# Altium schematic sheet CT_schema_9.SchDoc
size 274 x 160 mm
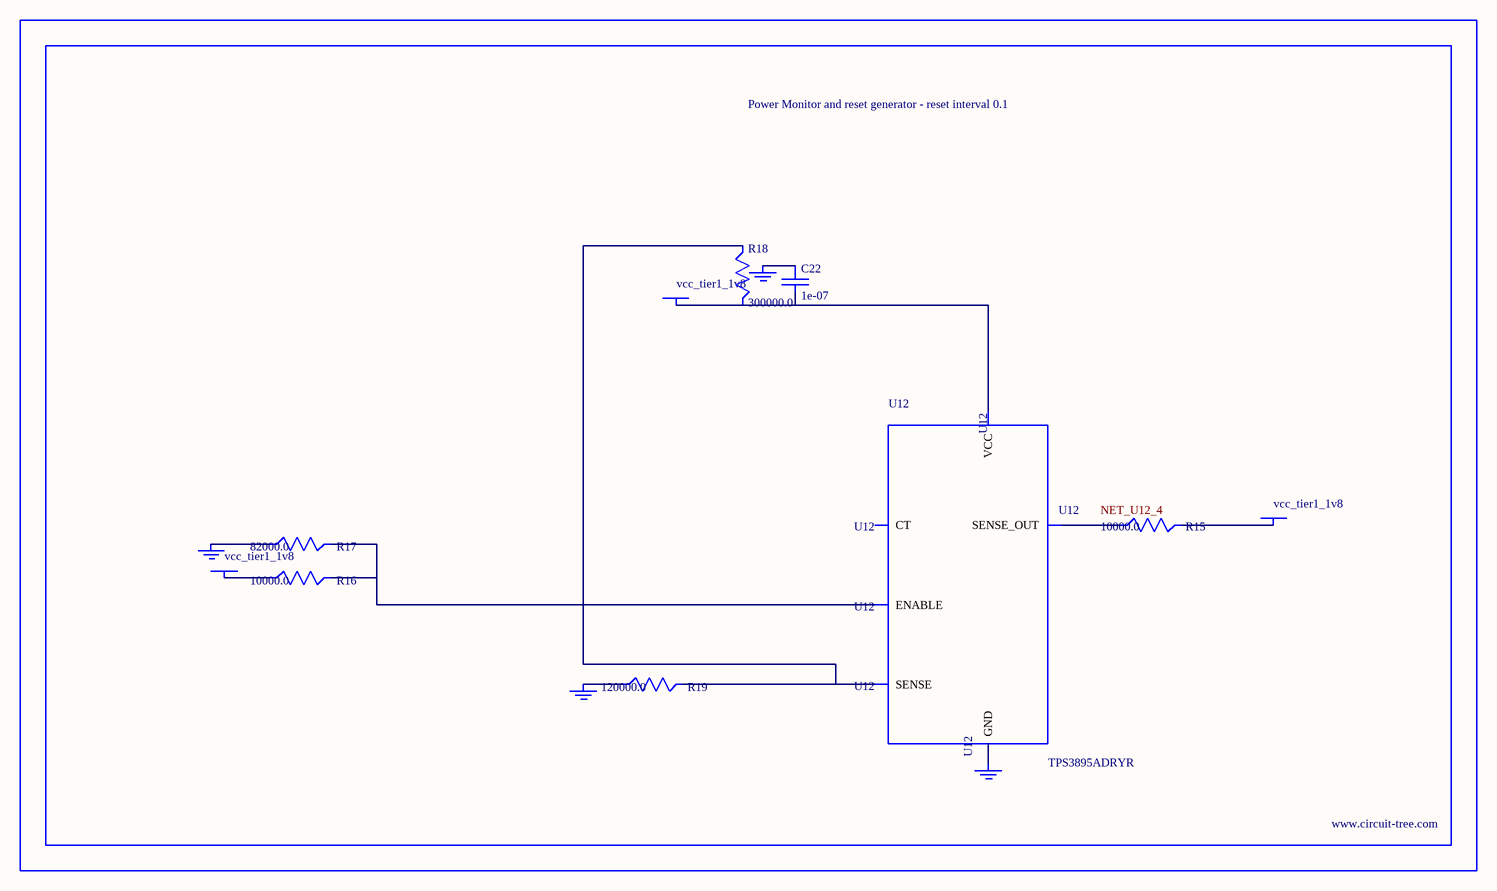
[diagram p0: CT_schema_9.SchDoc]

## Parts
BORDER8  (no value)
C22  1e-07  [C0402]
GND_INSTANCE_8_0  (no value)
GND_INSTANCE_8_1  (no value)
GND_INSTANCE_8_2  (no value)
GND_INSTANCE_8_3  (no value)
POWER_INSTANCE_8_0  vcc_tier1_1v8
POWER_INSTANCE_8_1  vcc_tier1_1v8
POWER_INSTANCE_8_2  vcc_tier1_1v8
R15  10000.0  [R0603]
R16  10000.0  [R0603]
R17  82000.0  [R0603]
R18  300000.0  [R0603]
R19  120000.0  [R0603]
U12  TPS3895ADRYR  [SON-6]

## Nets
NetC22_1: C22.1 GND_INSTANCE_8_2.0(GND)
NetC22_2: C22.2 POWER_INSTANCE_8_2.0(PWR) R18.2 U12.6(VCC)
NetGND_INSTANCE_8_0_0: GND_INSTANCE_8_0.0(GND) R17.1
NetGND_INSTANCE_8_1_0: GND_INSTANCE_8_1.0(GND) R19.1
NetGND_INSTANCE_8_3_0: GND_INSTANCE_8_3.0(GND) U12.2(GND)
NetPOWER_INSTANCE_8_0_0: POWER_INSTANCE_8_0.0(PWR) R16.1
NetPOWER_INSTANCE_8_1_0: POWER_INSTANCE_8_1.0(PWR) R15.2
NetR15_1: R15.1 U12.4(SENSE_OUT)
NetR16_2: R16.2 R17.2 U12.1(ENABLE)
NetR18_1: R18.1 R19.2 U12.3(SENSE)

Not connected (* = marked no-connect by the designer): U12 5(CT)

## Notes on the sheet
- Labels drawn without touching a wire or pin: NET_U12_4

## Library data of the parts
BORDER8 = BORDER_PAGE8
C22 = C0402C104K3RACTU
GND_INSTANCE_8_0-GND_INSTANCE_8_3 = GND
POWER_INSTANCE_8_0-POWER_INSTANCE_8_2 = PWR
R15 R16 = RC0603JR-0710KL
R17 = RC0603JR-0782KL
R18 = RC0603JR-07300KL
R19 = RC0603JR-07120KL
